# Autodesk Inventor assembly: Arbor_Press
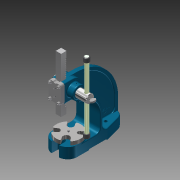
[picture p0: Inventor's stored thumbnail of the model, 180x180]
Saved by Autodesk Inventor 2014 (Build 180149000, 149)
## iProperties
Shininess: 64.0
Length Units: 11272
Angle Units: 11279
Time Units: 11290
Mass Units: 11286
Length Display Precision: 3
Angle Display Precision: 2
Compacted: True
Part Number: Arbor_Press
Document SubType Name: Assembly
Created: 2003-11
Designer: Autodesk, Inc
Manufacturer: Standard
Standards Organization: Custom
Mass: 8057.89 g
Surface Area: 2435.26 cm^2
Volume: 1030.81 cm^3
Density: 7.81702 g/cm^3
Density: 0.0
Volumn: 0.0
Area: 0.0
PropertySet Name: Model Information
Control State: 0
Master: False
Checked Out: False
Title: Arbor Press
Author: Autodesk, Inc
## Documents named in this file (15)
- C:\Users\iTools\Desktop\tutorial files\Arbor Press\Arbor_Press.iam
- C:\Users\iTools\Desktop\tutorial files\Arbor Press\Components\Arbor_Frame.ipt
- C:\Users\iTools\Desktop\tutorial files\Arbor Press\Components\COLLAR.ipt
- C:\Users\iTools\Desktop\tutorial files\Arbor Press\Components\PINION SHAFT.ipt
- C:\Users\iTools\Desktop\tutorial files\Arbor Press\Components\LEVER ARM.ipt
- C:\Users\iTools\Desktop\tutorial files\Arbor Press\Components\THUMB SCREW.ipt
- C:\Users\iTools\Desktop\tutorial files\Arbor Press\Components\GIB PLATE.ipt
- C:\Users\iTools\Desktop\tutorial files\Arbor Press\Components\GROOVE PIN.ipt
- C:\Users\iTools\Desktop\tutorial files\Arbor Press\Components\TABLE PLATE.ipt
- C:\Users\iTools\Desktop\tutorial files\Arbor Press\Components\RAM.ipt
- C:\Users\iTools\Desktop\tutorial files\Arbor Press\Components\HANDLE CAP.ipt
- C:\Users\iTools\Desktop\tutorial files\Arbor Press\Components\FACE PLATE.ipt
- C:\Users\iTools\Desktop\tutorial files\Arbor Press\Standard Parts\ANSI B18.3 - 1_4-20 UNC - 0.875(31).ipt
- C:\Users\iTools\Desktop\tutorial files\Arbor Press\Standard Parts\ISO 4026 - M5 x 16ISO.ipt
- C:\Users\iTools\Desktop\tutorial files\Arbor Press\Standard Parts\ISO 4766 - M5 x 5ISO.ipt
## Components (21 placed, 14 different names)
1. Arbor_Frame:1 — Mate:1, Insert:3, Insert:6, Insert:7, Angle SHAFT TURN, Angle PLATE, Flush:7, Mate:14, Flush:11, Flush:12, Mate:15, Flush:13, Flush:23, Flush:24
2. FACE PLATE:1 — Flush:2, Mate:14, Flush:9, Flush:10, Flush:12, Flush:23, Flush:24
3. PINION SHAFT:1 — Mate:3, Insert:7, Rotation/Translation:1, Angle SHAFT TURN, Mate:12, Insert:12, Mate:17
4. LEVER ARM:1 — Mate:3, Mate:12
5. THUMB SCREW:1 — Insert:12, Mate:17
6. TABLE PLATE:1 — Insert:3, Mate:5, Angle PLATE, Mate HEIGHT
7. RAM:1 — Mate:1, Rotation/Translation:1, Flush:11, Mate HEIGHT
8. HANDLE CAP:1
9. HANDLE CAP:2
10. COLLAR:1 — Insert:6, Mate:30, Tangent:1
11. GIB PLATE:1 — Flush:2, Flush:9, Flush:10
12. GROOVE PIN:1 — Mate:5, Flush:7
13. Hexagon Socket Head Cap Screw - Inch 1/4 - 20 UNC - 7/8:1
14. Hexagon Socket Head Cap Screw - Inch 1/4 - 20 UNC - 7/8:2
15. Hexagon Socket Head Cap Screw - Inch 1/4 - 20 UNC - 7/8:3
16. Hexagon Socket Head Cap Screw - Inch 1/4 - 20 UNC - 7/8:4
17. ISO 4026 M5 x 16:1
18. ISO 4026 M5 x 16:2
19. ISO 4026 M5 x 16:3
20. ISO 4026 M5 x 16:4
21. ISO 4766 M5 x 5:1 — Mate:30, Tangent:1
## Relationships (26: Mate 9, Flush 9, Insert 4, Angle 2, RelateRotateTranslate 1, Tangent 1)
- Mate:1: Arbor_Frame:1 ↔ RAM:1
- Insert:3: Arbor_Frame:1 ↔ TABLE PLATE:1
- Mate:3: PINION SHAFT:1 ↔ LEVER ARM:1
- Insert:6: Arbor_Frame:1 ↔ COLLAR:1
- Mate:5: TABLE PLATE:1 ↔ GROOVE PIN:1
- Insert:7: Arbor_Frame:1 ↔ PINION SHAFT:1
- Flush:2: FACE PLATE:1 ↔ GIB PLATE:1
- Rotation/Translation:1 [RelateRotateTranslate]: PINION SHAFT:1 ↔ RAM:1
- Angle SHAFT TURN: Arbor_Frame:1 ↔ PINION SHAFT:1
- Angle PLATE: Arbor_Frame:1 ↔ TABLE PLATE:1
- Mate:12: PINION SHAFT:1 ↔ LEVER ARM:1
- Flush:7: Arbor_Frame:1 ↔ GROOVE PIN:1
- Mate:14: Arbor_Frame:1 ↔ FACE PLATE:1
- Flush:9: FACE PLATE:1 ↔ GIB PLATE:1
- Flush:10: FACE PLATE:1 ↔ GIB PLATE:1
- Flush:11: Arbor_Frame:1 ↔ RAM:1
- Flush:12: Arbor_Frame:1 ↔ FACE PLATE:1
- Mate:15: Arbor_Frame:1
- Flush:13: Arbor_Frame:1
- Insert:12: PINION SHAFT:1 ↔ THUMB SCREW:1
- Mate:17: PINION SHAFT:1 ↔ THUMB SCREW:1
- Flush:23: Arbor_Frame:1 ↔ FACE PLATE:1
- Flush:24: Arbor_Frame:1 ↔ FACE PLATE:1
- Mate HEIGHT: TABLE PLATE:1 ↔ RAM:1
- Mate:30: COLLAR:1 ↔ ISO 4766 M5 x 5:1
- Tangent:1: COLLAR:1 ↔ ISO 4766 M5 x 5:1
